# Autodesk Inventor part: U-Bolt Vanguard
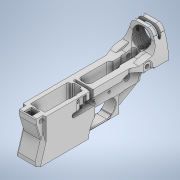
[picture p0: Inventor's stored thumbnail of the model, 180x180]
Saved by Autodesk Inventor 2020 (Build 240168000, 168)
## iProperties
Created: 2020-05
Part Number: U-Bolt Vanguard
Material: Generic
Document SubType Name: Modeling
Designer: Iv. Tr.
Density: 1 g/cm^3
Appearance: Default
Title: D:\~~GatCad\Vanguard_Fixed_Dimensions\STEP\U-Bolt Vanguard.stp
Author: johne
Revision Number: 3LAST_VERSION
Sending System: Autodesk Inventor 2020
Preprocessor: ST-DEVELOPER v18
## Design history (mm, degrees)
feature "Solid3"
body "Solid1"
